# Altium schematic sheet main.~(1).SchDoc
size A
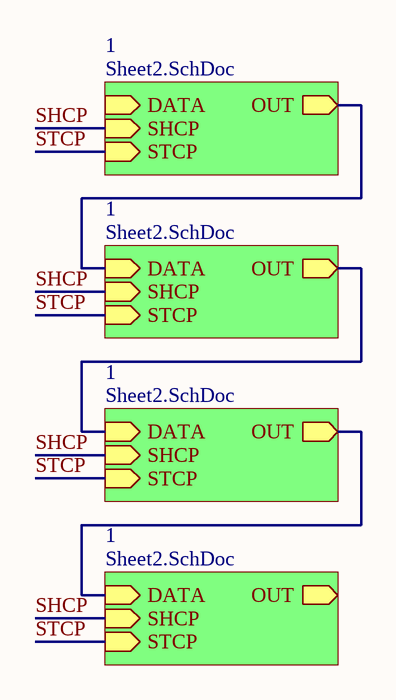
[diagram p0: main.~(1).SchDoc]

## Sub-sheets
1 = Sheet2.SchDoc: DATA (in), SHCP (in), STCP (in), OUT (out)
1 = Sheet2.SchDoc: DATA (in), SHCP (in), STCP (in), OUT (out)
1 = Sheet2.SchDoc: DATA (in), SHCP (in), STCP (in), OUT (out)
1 = Sheet2.SchDoc: DATA (in), SHCP (in), STCP (in), OUT (out)

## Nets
SHCP: sheet 1/SHCP, sheet 1/SHCP, sheet 1/SHCP, sheet 1/SHCP
STCP: sheet 1/STCP, sheet 1/STCP, sheet 1/STCP, sheet 1/STCP
(unnamed): sheet 1/OUT, sheet 1/DATA
(unnamed): sheet 1/OUT, sheet 1/DATA  [a separate net that carries the same name]
(unnamed): sheet 1/OUT, sheet 1/DATA  [a separate net that carries the same name]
